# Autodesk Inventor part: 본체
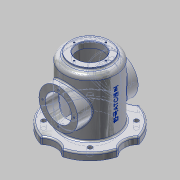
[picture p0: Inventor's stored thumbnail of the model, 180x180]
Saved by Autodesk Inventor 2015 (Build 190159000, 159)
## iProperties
Created: 2022-04
Part Number: 본체
Material: 알루미늄 6061
Document SubType Name: Modeling
Designer: User
Mass: 1517.6 g
Surface Area: 1256.99 cm^2
Volume: 562.075 cm^3
Density: 2.7 g/cm^3
Appearance: 알루미늄 - 평지
Author: User
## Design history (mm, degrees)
sketch "스케치2"
  geometry: L1 (53, 66)-(-53, 66); L2 (-53, 66)-(-53, -66); L3 (-53, -66)-(53, -66); L4 (53, -66)-(53, 66); L5 (53, 66)-(-53, -66); L6 (-53, 66)-(53, -66); 3 further points
  constraints: 12 end point, 4 midpoint, 2 parallel, 1 horizontal, 1 perpendicular
  dimensions: "d0" = 132 distance of L3.end L1.start; "d1" = 106 distance of L1.start L1.end
extrude "돌출1" new body sketch "스케치2" distance "d2" = 106; taper "d3" = 0 deg
sketch "스케치3" dims "d5" = 106
  geometry: L1 (0, 0)-(106, 0) reference; L2 (0, 0)-(0, 106) reference; L3 (0, 106)-(106, 106) reference; L4 (106, 0)-(106, 106) reference; 4 further points
  constraints: 2 midpoint, 2 vertical alignment, 2 other
extrude "돌출2" cut sketch "스케치3" stored distance "d6" = 106; taper "d7" = 0 deg
sketch "스케치4"
  geometry: C1 r 40 at (0, 0); 1 further point
  constraints: 1 centre point, 1 vertical alignment
  dimensions: "d8" = 80 diameter of C1; "d9" = 53 distance of point (0, -53) C1.centre
extrude "돌출3" join sketch "스케치4" distance "d10" = 5; taper "d11" = 0 deg
sketch "스케치5"
  geometry: C1 r 27 at (0, 0); 1 further point
  constraints: 1 centre point, 1 vertical alignment
  dimensions: "d12" = 54 diameter of C1; "d13" = 53 distance of point (0, -53) C1.centre
extrude "돌출4" cut sketch "스케치5" distance "d14" = 13; taper "d15" = 0 deg
chamfer "모따기1" distance "d16" = 1; stored, may be unused: second distance "d17" = 2, angle "d18" = 45 deg
sketch "스케치6"
  geometry: C1 r 45 at (0, 0); 1 further point
  constraints: 1 centre point, 1 vertical alignment
  dimensions: "d19" = 90 diameter of C1; "d20" = 53 distance of C1.centre point (0, -53)
extrude "돌출5" cut sketch "스케치6" distance "d21" = 124; taper "d22" = 0 deg
node "작업 평면1"
node "작업 평면2"
sketch "스케치7"
  geometry: L1 (-53, -66)-(53, -66) reference; C1 r 40 at (0, 2); 1 further point
  constraints: 1 centre point, 1 vertical alignment
  dimensions: "d25" = 80 diameter of C1; "d26" = 68 distance from line of L1 C1.centre
extrude "돌출6" join sketch "스케치7" stored distance "d27" = 124; taper "d28" = 0 deg
sketch "스케치8"
  geometry: L1 (-53, -68)-(53, -68) reference; C1 r 27 at (0, 0); 1 further point
  constraints: 1 centre point, 1 vertical alignment
  dimensions: "d29" = 54 diameter of C1; "d30" = 68 distance from line of L1 C1.centre
extrude "돌출7" cut sketch "스케치8" stored distance "d31" = 124; taper "d32" = 0 deg
sketch "스케치9" dims "d33" = 65
  geometry: L1 (-53, -68)-(53, -68) reference; L2 (0, 0)-(0, 32.5); 2 further points
  constraints: 2 end point, 2 vertical alignment, 1 coincident, 1 vertical, 2 other
  dimensions: "d34" = 68 distance from line of L1 L2.start
hole "구멍1" sketch "스케치9" at (0, 32.5) diameter "d35" = 3.242; stored, may be unused: countersink angle "d39" = 90 deg, drill point angle "d41" = 118 deg; dims "d36" = 8, "d37" = 4, "d38" = 2, "d40" = 10
node "작업 평면3"
sketch "스케치10"
  geometry: L1 (-53, -66)-(53, -66) reference; C1 r 40 at (0, 2); 1 further point
  constraints: 1 centre point, 1 vertical alignment
  dimensions: "d46" = 80 diameter of C1; "d47" = 68 distance from line of L1 C1.centre
extrude "돌출8" join sketch "스케치10" stored distance "d48" = 124; taper "d49" = 0 deg
sketch "스케치11"
  geometry: L1 (53, 68)-(-53, 68) reference; C1 r 27 at (0, 0); 1 further point
  constraints: 1 centre point, 1 vertical alignment
  dimensions: "d50" = 54 diameter of C1; "d51" = 68 distance from line of L1 C1.centre
extrude "돌출9" cut sketch "스케치11" stored distance "d52" = 124; taper "d53" = 0 deg
sketch "스케치12" dims "d54" = 65
  geometry: L1 (53, 68)-(-53, 68) reference; L2 (0, 0)-(0, -32.5); 2 further points
  constraints: 2 end point, 2 vertical alignment, 1 coincident, 1 vertical, 2 other
  dimensions: "d55" = 68 distance from line of L1 L2.start
hole "구멍2" sketch "스케치12" at (0, -32.5) diameter "d56" = 3.242; stored, may be unused: countersink angle "d60" = 90 deg, drill point angle "d62" = 118 deg; dims "d57" = 8, "d58" = 4, "d59" = 2, "d61" = 10
sketch "스케치13" dims "d66" = 65
  geometry: L1 (0, 0)-(0, -32.5); 2 further points
  constraints: 2 end point, 2 vertical alignment, 1 coincident, 1 vertical, 2 other
  dimensions: "d67" = 53 distance of L1.start point (0, -53)
hole "구멍3" sketch "스케치13" at (0, -32.5) diameter "d68" = 3.242; stored, may be unused: countersink angle "d72" = 90 deg, drill point angle "d74" = 118 deg; dims "d69" = 8, "d70" = 4, "d71" = 2, "d73" = 10
node "작업 평면4"
sketch "스케치14"
  geometry: C1 r 28 at (0, 53) reference; A1 r 30 centre (0, -47) between (21.541, -26.12) and (-21.541, -26.12); A2 r 30 centre (-100, 53) between (-79.12, 31.459) and (-79.12, 74.541); A3 r 30 centre (0, 153) between (-21.541, 132.12) and (21.541, 132.12); A4 r 30 centre (100, 53) between (79.12, 74.541) and (79.12, 31.459); A5 r 82 centre (0, 53) between (-79.12, 31.459) and (-21.541, -26.12); A6 r 82 centre (0, 53) between (-21.541, 132.12) and (-79.12, 74.541); A7 r 82 centre (0, 53) between (21.541, -26.12) and (79.12, 31.459); A8 r 82 centre (0, 53) between (79.12, 74.541) and (21.541, 132.12); 1 further point
  constraints: 16 point on circle, 8 centre point, 2 horizontal alignment, 2 vertical alignment, 1 coincident
  dimensions: "d80" = 60 diameter of A1; "d81" = 60 diameter of A2; "d82" = 60 diameter of A3; "d83" = 60 diameter of A4; "d84" = 100 distance of C1.centre A1.centre; "d85" = 100 distance of A3.centre C1.centre; "d86" = 100 distance of A4.centre C1.centre; "d87" = 100 distance of A2.centre C1.centre; "d88" = 82 radius of A7; "d89" = 82 radius of A8; "d90" = 82 radius of A6; "d91" = 82 radius of A5
extrude "돌출10" join sketch "스케치14" distance "d92" = 14; taper "d93" = 0 deg
sketch "스케치15"
  geometry: C1 r 45 at (0, 53); 1 further point
  constraints: 1 centre point, 1 vertical alignment
  dimensions: "d94" = 90 diameter of C1; "d95" = 53 distance of C1.centre point (0, 0)
extrude "돌출11" cut sketch "스케치15" distance "d96" = 14; taper "d97" = 0 deg
sketch "스케치16" dims "d98" = 135
  geometry: L1 (0, 53)-(-47.73, 5.27); L2 (0, 53)-(-47.73, 100.73); L3 (0, 53)-(47.73, 5.27); L4 (0, 53)-(47.73, 100.73); L5 (0, 53)-(0, -14.5); L6 (0, 53)-(0, 120.5); L7 (0, 53)-(-67.5, 53); L8 (0, 53)-(67.5, 53); C1 r 4.5 at (-47.73, 5.27); C2 r 4.5 at (-47.73, 100.73); C3 r 4.5 at (47.73, 100.73); C4 r 4.5 at (47.73, 5.27); 1 further point
  constraints: 16 end point, 4 centre point, 4 coincident, 2 horizontal, 2 vertical, 1 vertical alignment, 10 other
  dimensions: "d99" = 53 distance of L1.start point (0, 0); "d100" = 45 deg angle of L2 L7; "d101" = 45 deg angle of L7 L1; "d103" = 45 deg angle of L8 L3; "d104" = 45 deg angle of L8 L4; "d105" = 9 diameter of C1; "d106" = 9 diameter of C2; "d107" = 9 diameter of C3; "d108" = 9 diameter of C4
extrude "돌출12" cut sketch "스케치16" distance "d109" = 14; taper "d110" = 0 deg
fillet "모깎기1" dims "d111" = 3
fillet "모깎기2" dims "d112" = 3
fillet "모깎기3" dims "d113" = 3
fillet "모깎기4" dims "d114" = 10
node "작업 평면5"
sketch "스케치17"
  geometry: L1 (32.643, -66)-(73.357, -66) reference; L2 (-12, 42)-(-12, -38) reference; 2 further points
  constraints: 1 other
  dimensions: "d116" = 70 distance from line of L1 point (53, 4); "d117" = 65 distance from line of point (53, 4) L2
feature "엠보싱1" sketch "스케치17" dims "d0" = 132, "d1" = 106, "d118" = 0.5, "d119" = 0
node "솔리드1"
pattern_circular "원형 패턴1" dims angle "d43" = 360 deg
pattern_circular "원형 패턴2" dims angle "d64" = 360 deg
pattern_circular "원형 패턴3" dims angle "d76" = 360 deg
other parameters: "d24" = -62, "d45" = 62, "d78" = -66, "d79" = 164, "d115" = 100.75
